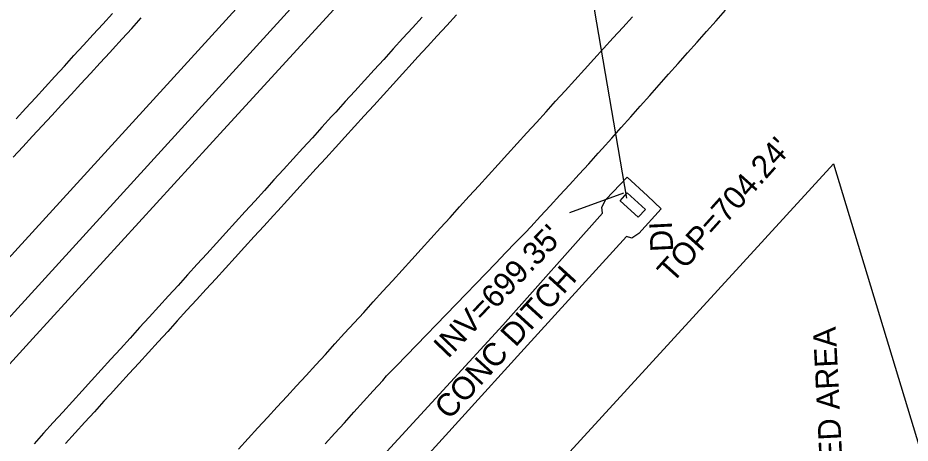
# Model space of a CAD drawing. Extents: x 1806071 to 1809844, y 912722 to 917035.
# Drawn here: x 1807205.8 to 1807362.2, y 913933 to 914007.5 of the extents above; entities that cross this region are included whole.
import ezdxf

# ---------------------------------------------------------------- set-up
doc = ezdxf.new("R2010")
doc.units = 0
for name, color, linetype in [('Exist Guardrail Cable Guide Rail', 7, 'Continuous'), ('Exist Horizontal Alignment', 7, 'Continuous'), ('Exist Other Culture Area Outline', 7, 'Continuous'), ('Exist Other Culture Area Outline Text', 7, 'Continuous'), ('Exist Roads EOP', 7, 'Continuous'), ('Exist Roads EOT', 7, 'Continuous'), ('Exist Structure Minor Drop Inlet', 7, 'Continuous'), ('Exist Structure Minor Drop Inlet Text', 7, 'Continuous'), ('Exist Structure Minor Drop Inlet Top Elevation', 7, 'Continuous'), ('Exist Structure Minor Paved Ditch or Gutter', 7, 'Continuous'), ('Exist Structure Minor Paved Ditch or Gutter Text', 7, 'Continuous'), ('Exist Structure Minor Pipes RCP 15 Inch', 7, 'Continuous'), ('Exist Structure Minor Pipes RCP 15 Inch Invert', 7, 'Continuous'), ('Exist Structure Minor Pipes RCP 24 Inch', 7, 'Continuous')]:
    doc.layers.add(name, color=color, linetype=linetype)

msp = doc.modelspace()

# ---------------------------------------------------------------- linework, layer by layer
at = {"layer": 'Exist Guardrail Cable Guide Rail'}
msp.add_lwpolyline([(1807036.39, 913762.23), (1807072.19, 913801.95), (1807107.96, 913840.99), (1807141.41, 913877.77), (1807177.33, 913917.12), (1807208.48, 913951.28), (1807242.54, 913988.57), (1807278.56, 914027.99), (1807303.96, 914056.09), (1807333.75, 914088.73), (1807369.98, 914128.47), (1807402.65, 914164.36), (1807436.63, 914201.71), (1807469.41, 914237.65), (1807504.53, 914276.04), (1807531.63, 914306.03), (1807569.88, 914348.1), (1807608.39, 914390.29), (1807638.77, 914423.86), (1807675.81, 914465.75)], dxfattribs=at)
at = {"layer": 'Exist Horizontal Alignment'}
msp.add_line((1806073.69, 912724.84), (1809374.2, 916346.52), dxfattribs=at)
msp.add_arc((1806875.73, 914308.35), 954.93, 296.15643, 355.38963, dxfattribs=at)
at = {"layer": 'Exist Other Culture Area Outline'}
msp.add_lwpolyline([(1807062.43, 913669.14), (1807348.8, 913981.91), (1807365.47, 913926.79), (1807376.75, 913863.76), (1807418.01, 913784.95), (1807457.77, 913738.07), (1807040.06, 913515.17)], dxfattribs=at)
at = {"layer": 'Exist Roads EOP'}
for points in [[(1807259.72, 913932.83), (1807261.4, 913934.69), (1807263.07, 913936.54), (1807264.75, 913938.4), (1807266.43, 913940.25), (1807268.1, 913942.11), (1807269.78, 913943.96), (1807270.47, 913944.74), (1807272.21, 913946.53), (1807273.95, 913948.33), (1807275.69, 913950.13), (1807277.43, 913951.93), (1807279.16, 913953.72), (1807280.9, 913955.52), (1807282.64, 913957.32), (1807284.38, 913959.12), (1807286.11, 913960.91), (1807287.85, 913962.71), (1807289.59, 913964.51), (1807291.33, 913966.3), (1807293.06, 913968.1), (1807294.8, 913969.9), (1807295.74, 913970.87), (1807297.43, 913972.72), (1807299.12, 913974.56), (1807300.81, 913976.4), (1807302.5, 913978.25), (1807304.19, 913980.09), (1807305.88, 913981.93), (1807307.56, 913983.78), (1807308.27, 913984.54), (1807309.93, 913986.41), (1807311.59, 913988.28), (1807313.25, 913990.15), (1807314.91, 913992.02), (1807316.57, 913993.89), (1807318.23, 913995.75), (1807319.89, 913997.62), (1807321.55, 913999.49), (1807323.22, 914001.36), (1807324.88, 914003.23), (1807326.54, 914005.1), (1807328.2, 914006.96), (1807329.86, 914008.83)], [(1807205.03, 913983.06), (1807206.72, 913984.9), (1807208.42, 913986.74), (1807210.11, 913988.57), (1807211.8, 913990.41), (1807213.5, 913992.25), (1807215.19, 913994.09), (1807216.88, 913995.93), (1807218.58, 913997.77), (1807220.27, 913999.61), (1807221.96, 914001.45), (1807222.44, 914001.97), (1807224.12, 914003.82), (1807225.79, 914005.67), (1807227.47, 914007.53)], [(1807276.69, 914007.62), (1807275.01, 914005.77), (1807273.32, 914003.92), (1807271.64, 914002.07), (1807269.96, 914000.22), (1807268.27, 913998.37), (1807266.59, 913996.52), (1807264.91, 913994.67), (1807263.23, 913992.83), (1807261.54, 913990.98), (1807260.83, 913990.19), (1807259.14, 913988.34), (1807257.46, 913986.49), (1807255.78, 913984.64), (1807254.1, 913982.79), (1807252.41, 913980.94), (1807250.73, 913979.09), (1807249.05, 913977.24), (1807247.37, 913975.4), (1807245.69, 913973.55), (1807244, 913971.7), (1807242.32, 913969.85), (1807240.64, 913968), (1807238.96, 913966.15), (1807237.27, 913964.3), (1807235.59, 913962.45), (1807233.91, 913960.6), (1807232.23, 913958.75), (1807230.55, 913956.9), (1807228.86, 913955.05), (1807227.18, 913953.2), (1807225.5, 913951.35), (1807223.82, 913949.51), (1807222.13, 913947.66), (1807220.45, 913945.81), (1807218.77, 913943.96), (1807217.09, 913942.11), (1807215.4, 913940.26), (1807213.72, 913938.41), (1807212.04, 913936.56), (1807210.36, 913934.71), (1807208.68, 913932.86)]]:
    msp.add_lwpolyline(points, dxfattribs=at)
at = {"layer": 'Exist Roads EOT'}
for points in [[(1807205.57, 913989.81), (1807207.25, 913991.66), (1807208.94, 913993.5), (1807210.62, 913995.35), (1807212.31, 913997.2), (1807214, 913999.04), (1807215.68, 914000.89), (1807217.37, 914002.74), (1807219.05, 914004.58), (1807220.74, 914006.43), (1807222.42, 914008.28)], [(1807282.71, 914008.03), (1807281.02, 914006.19), (1807279.33, 914004.34), (1807277.65, 914002.5), (1807275.96, 914000.65), (1807274.96, 913999.55), (1807273.27, 913997.7), (1807271.59, 913995.86), (1807269.91, 913994.01), (1807268.22, 913992.16), (1807266.54, 913990.31), (1807264.85, 913988.46), (1807263.17, 913986.62), (1807261.49, 913984.77), (1807259.8, 913982.92), (1807258.12, 913981.07), (1807256.43, 913979.22), (1807254.75, 913977.38), (1807253.07, 913975.53), (1807251.38, 913973.68), (1807250.63, 913972.86), (1807248.95, 913971.01), (1807247.27, 913969.17), (1807245.58, 913967.32), (1807243.9, 913965.47), (1807242.21, 913963.62), (1807240.53, 913961.78), (1807238.84, 913959.93), (1807237.16, 913958.08), (1807235.47, 913956.24), (1807233.79, 913954.39), (1807232.1, 913952.54), (1807230.42, 913950.69), (1807228.73, 913948.85), (1807227.05, 913947), (1807225.36, 913945.15), (1807223.68, 913943.31), (1807222, 913941.46), (1807220.94, 913940.3), (1807219.25, 913938.45), (1807217.57, 913936.61), (1807215.88, 913934.76), (1807214.2, 913932.91)], [(1807244.54, 913931.92), (1807246.23, 913933.77), (1807247.92, 913935.61), (1807249.61, 913937.46), (1807251.29, 913939.3), (1807252.98, 913941.15), (1807254.67, 913942.99), (1807256.36, 913944.83), (1807258.04, 913946.68), (1807259.73, 913948.52), (1807261.42, 913950.37), (1807263.11, 913952.21), (1807264.77, 913954.03), (1807266.45, 913955.88), (1807268.14, 913957.73), (1807269.82, 913959.58), (1807271.5, 913961.43), (1807273.18, 913963.28), (1807274.86, 913965.13), (1807276.54, 913966.98), (1807278.22, 913968.83), (1807279.91, 913970.68), (1807281.59, 913972.53), (1807283.27, 913974.38), (1807284.95, 913976.23), (1807286.63, 913978.08), (1807288.31, 913979.93), (1807289.99, 913981.78), (1807291.68, 913983.63), (1807293.36, 913985.48), (1807295.04, 913987.33), (1807296.72, 913989.18), (1807298.4, 913991.03), (1807300.08, 913992.88), (1807301.76, 913994.73), (1807303.44, 913996.58), (1807305.13, 913998.43), (1807306.81, 914000.28), (1807308.49, 914002.13), (1807310.17, 914003.98), (1807311.85, 914005.83), (1807313.53, 914007.68)]]:
    msp.add_lwpolyline(points, dxfattribs=at)
at = {"layer": 'Exist Structure Minor Drop Inlet'}
msp.add_lwpolyline([(1807312.65, 913976.81), (1807315.82, 913973.92), (1807314.56, 913972.54), (1807311.39, 913975.43)], close=True, dxfattribs=at)
at = {"layer": 'Exist Structure Minor Paved Ditch or Gutter'}
for points in [[(1807308.3, 913973.28), (1807308.2, 913974.35), (1807308.87, 913975.65), (1807312.61, 913979.58), (1807316.16, 913976.31), (1807318.58, 913974.03), (1807314.66, 913969.69), (1807313.42, 913968.88), (1807312.51, 913969.2)], [(1807308.3, 913973.28), (1807290.82, 913953.65), (1807257.41, 913917.25), (1807223.08, 913879.6), (1807225.49, 913877.79), (1807227.7, 913876.13), (1807261.8, 913913.4), (1807294.58, 913949.48), (1807312.51, 913969.2)]]:
    msp.add_lwpolyline(points, dxfattribs=at)
at = {"layer": 'Exist Structure Minor Pipes RCP 15 Inch'}
msp.add_line((1807312.54, 913975.92), (1807298.78, 914056.46), dxfattribs=at)
at = {"layer": 'Exist Structure Minor Pipes RCP 15 Inch Invert'}
msp.add_line((1807311.98, 913976.76), (1807302.52, 913973.35), dxfattribs=at)
at = {"layer": 'Exist Structure Minor Pipes RCP 24 Inch'}
msp.add_line((1807297.72, 914057.54), (1806961.96, 913688.88), dxfattribs=at)

# ---------------------------------------------------------------- texts
at = {"layer": 'Exist Other Culture Area Outline Text'}
msp.add_text('CULTIVATED AREA', height=4, rotation=92.8422, dxfattribs=at).set_placement((1807351.61, 913904.15))
at = {"layer": 'Exist Structure Minor Drop Inlet Text'}
msp.add_text('DI', height=4, rotation=92.8422, dxfattribs=at).set_placement((1807320.72, 913966.59))
at = {"layer": 'Exist Structure Minor Drop Inlet Top Elevation'}
msp.add_text("TOP=704.24'", height=4, rotation=48.1297, dxfattribs=at).set_placement((1807320.54, 913960.84))
at = {"layer": 'Exist Structure Minor Paved Ditch or Gutter Text'}
msp.add_text('CONC DITCH', height=4, rotation=47.7451, dxfattribs=at).set_placement((1807281.45, 913936.89))
at = {"layer": 'Exist Structure Minor Pipes RCP 15 Inch Invert'}
msp.add_text("INV=699.35'", height=4, rotation=46.2327, dxfattribs=at).set_placement((1807281.21, 913947.62))

doc.saveas('drawing.dxf')
